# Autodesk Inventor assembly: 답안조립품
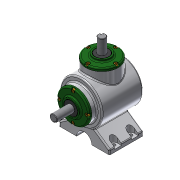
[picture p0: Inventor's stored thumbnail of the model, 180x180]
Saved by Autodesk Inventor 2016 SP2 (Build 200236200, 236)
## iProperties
Created: 2017-04
Part Number: 답안조립품
Material: 일반
Document SubType Name: Assembly
Designer: H
Author: H
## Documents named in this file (14)
- C:\Users\CAMTIC\Desktop\470407V1021\답안조립품.iam
- C:\Users\CAMTIC\Desktop\470407V1021\1-본체.ipt
- C:\Users\CAMTIC\Desktop\470407V1021\메인 베벨기어.ipt
- C:\Users\CAMTIC\Desktop\470407V1021\메인 축.ipt
- 메인 축.ipt
- C:\Users\CAMTIC\Desktop\470407V1021\베어링 6203.ipt
- C:\Users\CAMTIC\Desktop\470407V1021\볼트 M4.ipt
- C:\Users\CAMTIC\Desktop\470407V1021\서브 베벨기어.ipt
- C:\Users\CAMTIC\Desktop\470407V1021\서브 축.ipt
- 서브 축.ipt
- C:\Users\CAMTIC\Desktop\470407V1021\오일실 17 32 8.ipt
- C:\Users\CAMTIC\Desktop\470407V1021\커버.ipt
- C:\Users\CAMTIC\Desktop\470407V1021\키 4x4.ipt
- C:\Users\CAMTIC\Desktop\470407V1021\키 5x5.ipt
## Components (1 placed, 1 different names)
1. 1-본체:1
